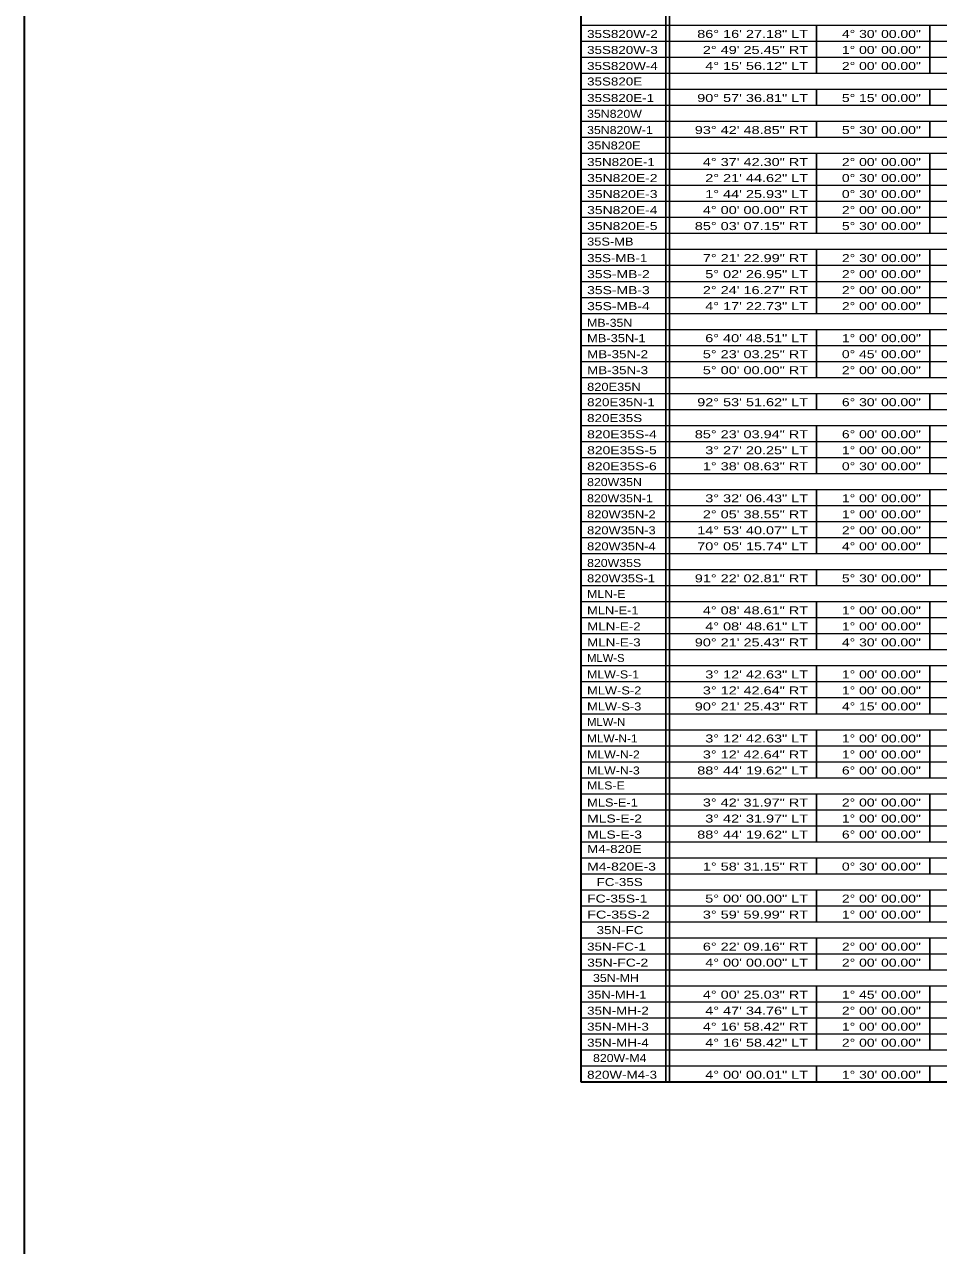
# Model space of a CAD drawing. Extents: x 1953053 to 1967065, y 7363860 to 7371201.
# Drawn here: x 1953053 to 1954423, y 7367530 to 7369361 of the extents above; entities that cross this region are included whole.
import ezdxf
from ezdxf.enums import TextEntityAlignment as Align

# ---------------------------------------------------------------- set-up
doc = ezdxf.new("R2010")
doc.units = 0
doc.header["$LTSCALE"] = 4.8
doc.layers.add('10', color=7, linetype='Continuous')
doc.layers.add('12', color=7, linetype='Continuous', lineweight=25)
doc.layers.add('62', color=7, linetype='Continuous', lineweight=35)

msp = doc.modelspace()

# ---------------------------------------------------------------- linework, layer by layer
at = {"layer": '12'}
for p, q in [((1954014.328, 7370136.079), (1954014.328, 7367775.748)), ((1954019.815, 7370136.079), (1954019.815, 7367775.748)), ((1954239.815, 7369359.748), (1954239.815, 7369287.748)), ((1954409.815, 7369359.748), (1954409.815, 7369287.748)), ((1954239.815, 7369263.748), (1954239.815, 7369239.748)), ((1954409.815, 7369263.748), (1954409.815, 7369239.748)), ((1954239.815, 7369215.748), (1954239.815, 7369191.748)), ((1954409.815, 7369215.748), (1954409.815, 7369191.748)), ((1954239.815, 7369167.748), (1954239.815, 7369047.748)), ((1954409.815, 7369167.748), (1954409.815, 7369047.748)), ((1954239.815, 7369023.748), (1954239.815, 7368927.748)), ((1954409.815, 7369023.748), (1954409.815, 7368927.748)), ((1954239.815, 7368903.748), (1954239.815, 7368831.748)), ((1954409.815, 7368903.748), (1954409.815, 7368831.748)), ((1954239.815, 7368807.748), (1954239.815, 7368783.748)), ((1954409.815, 7368807.748), (1954409.815, 7368783.748)), ((1954239.815, 7368759.748), (1954239.815, 7368687.748)), ((1954409.815, 7368759.748), (1954409.815, 7368687.748)), ((1954239.815, 7368663.748), (1954239.815, 7368567.748)), ((1954409.815, 7368663.748), (1954409.815, 7368567.748)), ((1954239.815, 7368543.748), (1954239.815, 7368519.748)), ((1954409.815, 7368543.748), (1954409.815, 7368519.748)), ((1954239.815, 7368495.748), (1954239.815, 7368423.748)), ((1954409.815, 7368495.748), (1954409.815, 7368423.748)), ((1954239.815, 7368399.748), (1954239.815, 7368327.748)), ((1954409.815, 7368399.748), (1954409.815, 7368327.748)), ((1954239.815, 7368303.748), (1954239.815, 7368231.748)), ((1954409.815, 7368303.748), (1954409.815, 7368231.748)), ((1954239.815, 7368207.748), (1954239.815, 7368135.748)), ((1954409.815, 7368207.748), (1954409.815, 7368135.748)), ((1954239.815, 7368111.748), (1954239.815, 7368087.748)), ((1954409.815, 7368111.748), (1954409.815, 7368087.748)), ((1954239.815, 7368063.748), (1954239.815, 7368015.748)), ((1954409.815, 7368063.748), (1954409.815, 7368015.748)), ((1954239.815, 7367991.748), (1954239.815, 7367943.748)), ((1954409.815, 7367991.748), (1954409.815, 7367943.748)), ((1954239.815, 7367919.748), (1954239.815, 7367823.748)), ((1954409.815, 7367919.748), (1954409.815, 7367823.748)), ((1954239.815, 7367799.748), (1954239.815, 7367775.748)), ((1954409.815, 7367799.748), (1954409.815, 7367775.748))]:
    msp.add_line(p, q, dxfattribs=at)
at = {"layer": '12', "lineweight": 35}
for p, q in [((1953886.483, 7370055.746), (1953886.483, 7367775.748)), ((1953886.483, 7367775.748), (1955609.815, 7367775.748))]:
    msp.add_line(p, q, dxfattribs=at)
at = {"layer": '12', "lineweight": 13}
for p, q in [((1953886.483, 7369359.748), (1955609.815, 7369359.748)), ((1953886.483, 7369335.748), (1955609.815, 7369335.748)), ((1953886.483, 7369311.748), (1955609.815, 7369311.748)), ((1953886.483, 7369287.748), (1955609.815, 7369287.748)), ((1953886.483, 7369263.748), (1955609.815, 7369263.748)), ((1953886.483, 7369239.748), (1955609.815, 7369239.748)), ((1953886.483, 7369215.748), (1955609.815, 7369215.748)), ((1953886.483, 7369191.748), (1955609.815, 7369191.748)), ((1953886.483, 7369167.748), (1955609.815, 7369167.748)), ((1953886.483, 7369143.748), (1955609.815, 7369143.748)), ((1953886.483, 7369119.748), (1955609.815, 7369119.748)), ((1953886.483, 7369095.748), (1955609.815, 7369095.748)), ((1953886.483, 7369071.748), (1955609.815, 7369071.748)), ((1953886.483, 7369047.748), (1955609.815, 7369047.748)), ((1953886.483, 7369023.748), (1955609.815, 7369023.748)), ((1953886.483, 7368999.748), (1955609.815, 7368999.748)), ((1953886.483, 7368975.748), (1955609.815, 7368975.748)), ((1953886.483, 7368951.748), (1955609.815, 7368951.748)), ((1953886.483, 7368927.748), (1955609.815, 7368927.748)), ((1953886.483, 7368903.748), (1955609.815, 7368903.748)), ((1953886.483, 7368879.748), (1955609.815, 7368879.748)), ((1953886.483, 7368855.748), (1955609.815, 7368855.748)), ((1953886.483, 7368831.748), (1955609.815, 7368831.748)), ((1953886.483, 7368807.748), (1955609.815, 7368807.748)), ((1953886.483, 7368783.748), (1955609.815, 7368783.748)), ((1953886.483, 7368759.748), (1955609.815, 7368759.748)), ((1953886.483, 7368735.748), (1955609.815, 7368735.748)), ((1953886.483, 7368711.748), (1955609.815, 7368711.748)), ((1953886.483, 7368687.748), (1955609.815, 7368687.748)), ((1953886.483, 7368663.748), (1955609.815, 7368663.748)), ((1953886.483, 7368639.748), (1955609.815, 7368639.748)), ((1953886.483, 7368615.748), (1955609.815, 7368615.748)), ((1953886.483, 7368591.748), (1955609.815, 7368591.748)), ((1953886.483, 7368567.748), (1955609.815, 7368567.748)), ((1953886.483, 7368543.748), (1955609.815, 7368543.748)), ((1953886.483, 7368519.748), (1955609.815, 7368519.748)), ((1953886.483, 7368495.748), (1955609.815, 7368495.748)), ((1953886.483, 7368471.748), (1955609.815, 7368471.748)), ((1953886.483, 7368447.748), (1955609.815, 7368447.748)), ((1953886.483, 7368423.748), (1955609.815, 7368423.748)), ((1953886.483, 7368399.748), (1955609.815, 7368399.748)), ((1953886.483, 7368375.748), (1955609.815, 7368375.748)), ((1953886.483, 7368351.748), (1955609.815, 7368351.748)), ((1953886.483, 7368327.748), (1955609.815, 7368327.748)), ((1953886.483, 7368303.748), (1955609.815, 7368303.748)), ((1953886.483, 7368279.748), (1955609.815, 7368279.748)), ((1953886.483, 7368255.748), (1955609.815, 7368255.748)), ((1953886.483, 7368231.748), (1955609.815, 7368231.748)), ((1953886.483, 7368207.748), (1955609.815, 7368207.748)), ((1953886.483, 7368183.748), (1955609.815, 7368183.748)), ((1953886.483, 7368159.748), (1955609.815, 7368159.748)), ((1953886.483, 7368135.748), (1955609.815, 7368135.748)), ((1953886.483, 7368111.748), (1955609.815, 7368111.748)), ((1953886.483, 7368087.748), (1955609.815, 7368087.748)), ((1953886.483, 7368063.748), (1955609.815, 7368063.748)), ((1953886.483, 7368039.748), (1955609.815, 7368039.748)), ((1953886.483, 7368015.748), (1955609.815, 7368015.748)), ((1953886.483, 7367991.748), (1955609.815, 7367991.748)), ((1953886.483, 7367967.748), (1955609.815, 7367967.748)), ((1953886.483, 7367943.748), (1955609.815, 7367943.748)), ((1953886.483, 7367919.748), (1955609.815, 7367919.748)), ((1953886.483, 7367895.748), (1955609.815, 7367895.748)), ((1953886.483, 7367871.748), (1955609.815, 7367871.748)), ((1953886.483, 7367847.748), (1955609.815, 7367847.748)), ((1953886.483, 7367823.748), (1955609.815, 7367823.748)), ((1953886.483, 7367823.748), (1955609.815, 7367823.748)), ((1953886.483, 7367799.748), (1955609.815, 7367799.748))]:
    msp.add_line(p, q, dxfattribs=at)
at = {"layer": '62'}
msp.add_lwpolyline([(1953052.784, 7371201.108), (1967065.314, 7371201.108), (1967065.314, 7363859.877), (1953052.784, 7363859.877)], close=True, dxfattribs=at)

# ---------------------------------------------------------------- texts
at = {"layer": '10'}
for s, width, p in [('35S820W-2', 1.25, (1953896.104, 7369340.577)), ('35S820W-3', 1.25, (1953896.104, 7369316.577)), ('35S820W-4', 1.25, (1953896.104, 7369292.577)), ('35S820E', 1.25, (1953896.104, 7369269.304)), ('35S820E-1', 1.25, (1953896.104, 7369244.577)), ('35N820W', 1.15, (1953896.104, 7369220.857)), ('35N820W-1', 1.15, (1953896.104, 7369196.577)), ('35N820E', 1.2, (1953896.104, 7369173.427)), ('35N820E-1', 1.25, (1953896.104, 7369148.577)), ('35N820E-2', 1.3, (1953896.104, 7369124.577)), ('35N820E-3', 1.3, (1953896.104, 7369100.577)), ('35N820E-4', 1.3, (1953896.104, 7369076.577)), ('35N820E-5', 1.3, (1953896.104, 7369052.577)), ('35S-MB', 1.2, (1953896.104, 7369029.327)), ('35S-MB-1', 1.25, (1953896.104, 7369004.577)), ('35S-MB-2', 1.3, (1953896.104, 7368980.577)), ('35S-MB-3', 1.3, (1953896.104, 7368956.577)), ('35S-MB-4', 1.3, (1953896.104, 7368932.577)), ('MB-35N', 1.15, (1953896.104, 7368907.59)), ('MB-35N-1', 1.2, (1953896.104, 7368884.577)), ('MB-35N-2', 1.25, (1953896.104, 7368860.577)), ('MB-35N-3', 1.25, (1953896.104, 7368836.577)), ('820E35N', 1.2, (1953896.104, 7368811.636)), ('820E35N-1', 1.25, (1953896.104, 7368788.577)), ('820E35S', 1.25, (1953896.104, 7368764.849)), ('820E35S-4', 1.3, (1953896.104, 7368740.577)), ('820E35S-5', 1.3, (1953896.104, 7368716.577)), ('820E35S-6', 1.3, (1953896.104, 7368692.577)), ('820W35N', 1.15, (1953896.104, 7368668.849)), ('820W35N-1', 1.15, (1953896.104, 7368644.575)), ('820W35N-2', 1.2, (1953896.104, 7368620.575)), ('820W35N-3', 1.2, (1953896.104, 7368596.575)), ('820W35N-4', 1.2, (1953896.104, 7368572.575)), ('820W35S', 1.15, (1953896.104, 7368547.636)), ('820W35S-1', 1.2, (1953896.104, 7368524.575)), ('MLN-E', 1.15, (1953896.104, 7368501.105)), ('MLN-E-1', 1.2, (1953896.104, 7368476.577)), ('MLN-E-2', 1.25, (1953896.104, 7368452.577)), ('MLN-E-3', 1.25, (1953896.104, 7368428.577)), ('MLW-S', 1.05, (1953896.104, 7368405.236)), ('MLW-S-1', 1.15, (1953896.104, 7368380.575)), ('MLW-S-2', 1.2, (1953896.104, 7368356.575)), ('MLW-S-3', 1.2, (1953896.104, 7368332.577)), ('MLW-N', 1.05, (1953896.104, 7368309.367)), ('MLW-N-1', 1.1, (1953896.104, 7368284.577)), ('MLW-N-2', 1.15, (1953896.104, 7368260.577)), ('MLW-N-3', 1.15, (1953896.104, 7368236.577)), ('MLS-E', 1.15, (1953896.104, 7368214.157)), ('MLS-E-1', 1.2, (1953896.104, 7368188.577)), ('MLS-E-2', 1.3, (1953896.104, 7368164.577)), ('MLS-E-3', 1.3, (1953896.104, 7368140.577)), ('M4-820E', 1.25, (1953896.104, 7368118.947)), ('M4-820E-3', 1.3, (1953896.104, 7368092.577)), ('FC-35S', 1.25, (1953910.344, 7368069.354)), ('FC-35S-1', 1.3, (1953896.104, 7368044.577)), ('FC-35S-2', 1.35, (1953896.104, 7368020.577)), ('35N-FC', 1.25, (1953910.344, 7367997.354)), ('35N-FC-1', 1.25, (1953896.104, 7367972.577)), ('35N-FC-2', 1.3, (1953896.104, 7367948.577)), ('35N-MH', 1.15, (1953905.01, 7367925.614)), ('35N-MH-1', 1.2, (1953896.104, 7367900.575)), ('35N-MH-2', 1.25, (1953896.104, 7367876.575)), ('35N-MH-3', 1.25, (1953896.104, 7367852.575)), ('35N-MH-4', 1.25, (1953896.104, 7367828.575)), ('820W-M4', 1.15, (1953905.01, 7367805.614)), ('820W-M4-3', 1.25, (1953896.104, 7367780.577))]:
    msp.add_text(s, height=12, dxfattribs=dict(at, width=width)).set_placement(p)
for s, width, p in [('86° 16\' 27.18" LT', 1.35, (1954227.337, 7369340.577)), ('4° 30\' 00.00"', 1.3, (1954396.332, 7369340.577)), ('2° 49\' 25.45" RT', 1.35, (1954227.337, 7369316.577)), ('1° 00\' 00.00"', 1.3, (1954396.332, 7369316.577)), ('4° 15\' 56.12" LT', 1.35, (1954227.337, 7369292.577)), ('2° 00\' 00.00"', 1.3, (1954396.332, 7369292.577)), ('90° 57\' 36.81" LT', 1.35, (1954227.337, 7369244.577)), ('5° 15\' 00.00"', 1.3, (1954396.332, 7369244.577)), ('93° 42\' 48.85" RT', 1.35, (1954227.337, 7369196.577)), ('5° 30\' 00.00"', 1.3, (1954396.332, 7369196.577)), ('4° 37\' 42.30" RT', 1.35, (1954227.337, 7369148.577)), ('2° 00\' 00.00"', 1.3, (1954396.332, 7369148.577)), ('2° 21\' 44.62" LT', 1.35, (1954227.337, 7369124.577)), ('0° 30\' 00.00"', 1.3, (1954396.332, 7369124.577)), ('1° 44\' 25.93" LT', 1.35, (1954227.337, 7369100.577)), ('0° 30\' 00.00"', 1.3, (1954396.332, 7369100.577)), ('4° 00\' 00.00" RT', 1.35, (1954227.337, 7369076.577)), ('2° 00\' 00.00"', 1.3, (1954396.332, 7369076.577)), ('85° 03\' 07.15" RT', 1.35, (1954227.337, 7369052.577)), ('5° 30\' 00.00"', 1.3, (1954396.332, 7369052.577)), ('7° 21\' 22.99" RT', 1.35, (1954227.337, 7369004.577)), ('2° 30\' 00.00"', 1.3, (1954396.332, 7369004.577)), ('5° 02\' 26.95" LT', 1.35, (1954227.337, 7368980.577)), ('2° 00\' 00.00"', 1.3, (1954396.332, 7368980.577)), ('2° 24\' 16.27" RT', 1.35, (1954227.337, 7368956.577)), ('2° 00\' 00.00"', 1.3, (1954396.332, 7368956.577)), ('4° 17\' 22.73" LT', 1.35, (1954227.337, 7368932.577)), ('2° 00\' 00.00"', 1.3, (1954396.332, 7368932.577)), ('6° 40\' 48.51" LT', 1.35, (1954227.337, 7368884.577)), ('1° 00\' 00.00"', 1.3, (1954396.332, 7368884.577)), ('5° 23\' 03.25" RT', 1.35, (1954227.337, 7368860.577)), ('0° 45\' 00.00"', 1.3, (1954396.332, 7368860.577)), ('5° 00\' 00.00" RT', 1.35, (1954227.337, 7368836.577)), ('2° 00\' 00.00"', 1.3, (1954396.332, 7368836.577)), ('92° 53\' 51.62" LT', 1.35, (1954227.337, 7368788.577)), ('6° 30\' 00.00"', 1.3, (1954396.332, 7368788.577)), ('85° 23\' 03.94" RT', 1.35, (1954227.337, 7368740.577)), ('6° 00\' 00.00"', 1.3, (1954396.332, 7368740.577)), ('3° 27\' 20.25" LT', 1.35, (1954227.337, 7368716.577)), ('1° 00\' 00.00"', 1.3, (1954396.332, 7368716.577)), ('1° 38\' 08.63" RT', 1.35, (1954227.337, 7368692.577)), ('0° 30\' 00.00"', 1.3, (1954396.332, 7368692.577)), ('3° 32\' 06.43" LT', 1.35, (1954227.337, 7368644.575)), ('1° 00\' 00.00"', 1.3, (1954396.332, 7368644.575)), ('2° 05\' 38.55" RT', 1.35, (1954227.337, 7368620.575)), ('1° 00\' 00.00"', 1.3, (1954396.332, 7368620.575)), ('14° 53\' 40.07" LT', 1.35, (1954227.337, 7368596.575)), ('2° 00\' 00.00"', 1.3, (1954396.332, 7368596.575)), ('70° 05\' 15.74" LT', 1.35, (1954227.337, 7368572.575)), ('4° 00\' 00.00"', 1.3, (1954396.332, 7368572.575)), ('91° 22\' 02.81" RT', 1.35, (1954227.337, 7368524.575)), ('5° 30\' 00.00"', 1.3, (1954396.332, 7368524.575)), ('4° 08\' 48.61" RT', 1.35, (1954227.337, 7368476.577)), ('1° 00\' 00.00"', 1.3, (1954396.332, 7368476.577)), ('4° 08\' 48.61" LT', 1.35, (1954227.337, 7368452.577)), ('1° 00\' 00.00"', 1.3, (1954396.332, 7368452.577)), ('90° 21\' 25.43" RT', 1.35, (1954227.337, 7368428.577)), ('4° 30\' 00.00"', 1.3, (1954396.332, 7368428.577)), ('3° 12\' 42.63" LT', 1.35, (1954227.337, 7368380.575)), ('1° 00\' 00.00"', 1.3, (1954396.332, 7368380.575)), ('3° 12\' 42.64" RT', 1.35, (1954227.337, 7368356.575)), ('1° 00\' 00.00"', 1.3, (1954396.332, 7368356.575)), ('90° 21\' 25.43" RT', 1.35, (1954227.337, 7368332.577)), ('4° 15\' 00.00"', 1.3, (1954396.332, 7368332.577)), ('3° 12\' 42.63" LT', 1.35, (1954227.337, 7368284.577)), ('1° 00\' 00.00"', 1.3, (1954396.332, 7368284.577)), ('3° 12\' 42.64" RT', 1.35, (1954227.337, 7368260.577)), ('1° 00\' 00.00"', 1.3, (1954396.332, 7368260.577)), ('88° 44\' 19.62" LT', 1.35, (1954227.337, 7368236.577)), ('6° 00\' 00.00"', 1.3, (1954396.332, 7368236.577)), ('3° 42\' 31.97" RT', 1.35, (1954227.337, 7368188.577)), ('2° 00\' 00.00"', 1.3, (1954396.332, 7368188.577)), ('3° 42\' 31.97" LT', 1.35, (1954227.337, 7368164.577)), ('1° 00\' 00.00"', 1.3, (1954396.332, 7368164.577)), ('88° 44\' 19.62" LT', 1.35, (1954227.337, 7368140.577)), ('6° 00\' 00.00"', 1.3, (1954396.332, 7368140.577)), ('1° 58\' 31.15" RT', 1.35, (1954227.337, 7368092.577)), ('0° 30\' 00.00"', 1.3, (1954396.332, 7368092.577)), ('5° 00\' 00.00" LT', 1.35, (1954227.337, 7368044.577)), ('2° 00\' 00.00"', 1.3, (1954396.332, 7368044.577)), ('3° 59\' 59.99" RT', 1.35, (1954227.337, 7368020.577)), ('1° 00\' 00.00"', 1.3, (1954396.332, 7368020.577)), ('6° 22\' 09.16" RT', 1.35, (1954227.337, 7367972.577)), ('2° 00\' 00.00"', 1.3, (1954396.332, 7367972.577)), ('4° 00\' 00.00" LT', 1.35, (1954227.337, 7367948.577)), ('2° 00\' 00.00"', 1.3, (1954396.332, 7367948.577)), ('4° 00\' 25.03" RT', 1.35, (1954227.337, 7367900.575)), ('1° 45\' 00.00"', 1.3, (1954396.332, 7367900.575)), ('4° 47\' 34.76" LT', 1.35, (1954227.337, 7367876.575)), ('2° 00\' 00.00"', 1.3, (1954396.332, 7367876.575)), ('4° 16\' 58.42" RT', 1.35, (1954227.337, 7367852.575)), ('1° 00\' 00.00"', 1.3, (1954396.332, 7367852.575)), ('4° 16\' 58.42" LT', 1.35, (1954227.337, 7367828.575)), ('2° 00\' 00.00"', 1.3, (1954396.332, 7367828.575)), ('4° 00\' 00.01" LT', 1.35, (1954227.337, 7367780.577)), ('1° 30\' 00.00"', 1.3, (1954396.332, 7367780.577))]:
    msp.add_text(s, height=12, dxfattribs=dict(at, width=width)).set_placement(p, align=Align.RIGHT)

doc.saveas('drawing.dxf')
